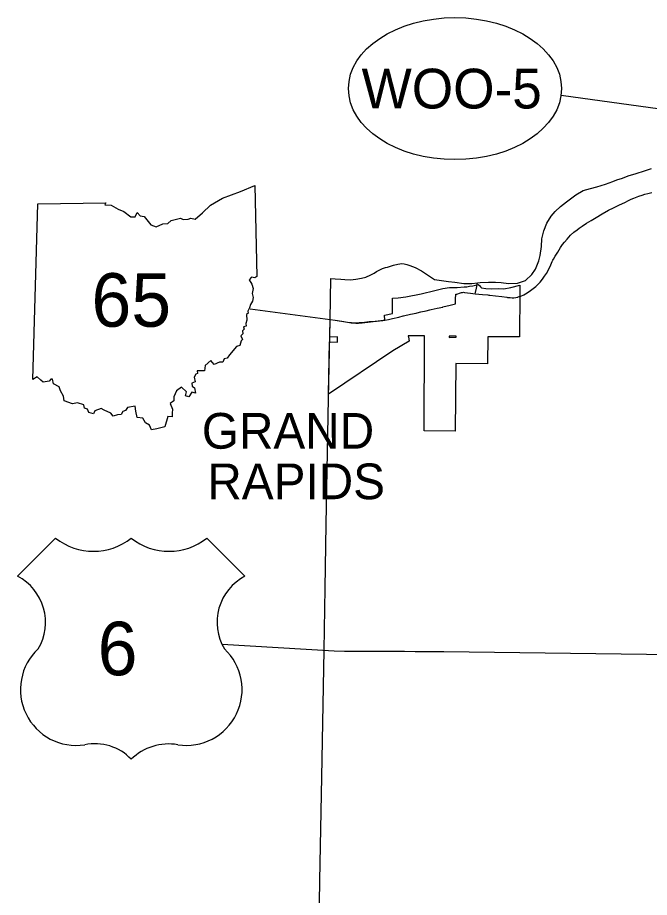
# Model space of a CAD drawing. Extents: x 0 to 851, y 0 to 440.
# Drawn here: x 185.2 to 229.7, y 193.8 to 255.7 of the extents above; entities that cross this region are included whole.
import ezdxf

# ---------------------------------------------------------------- set-up
doc = ezdxf.new("R2010")
doc.units = 0
for name, color, linetype in [('DV_X_Corp_Line', 7, 'Continuous'), ('GM_X_Corporation_Text', 7, 'Continuous'), ('GM_X_County', 7, 'Continuous'), ('GM_X_State_Route', 7, 'Continuous'), ('GM_X_US_Route', 7, 'Continuous'), ('PV_P_Text', 7, 'Continuous'), ('SH_Data', 7, 'Continuous')]:
    doc.layers.add(name, color=color, linetype=linetype)

msp = doc.modelspace()

# ---------------------------------------------------------------- linework, layer by layer
at = {"layer": 'DV_X_Corp_Line'}
for points in [[(207.099, 229.174), (207.166, 232.861), (207.728, 232.851), (207.727, 233.209), (207.172, 233.196), (207.194, 234.435), (207.555, 234.386), (208.426, 234.255), (208.697, 234.216), (208.861, 234.196), (209.001, 234.183), (209.189, 234.182), (209.452, 234.203), (209.867, 234.251), (210.228, 234.29), (210.903, 234.365), (211.063, 234.39), (211.022, 234.744), (211.59, 234.85), (211.6, 235.946), (211.998, 235.975), (212.541, 236.039), (213.614, 236.257), (214.57, 236.473), (215.131, 236.63), (215.604, 236.701), (216.143, 236.694), (216.632, 236.736), (216.832, 236.736), (217.007, 236.778), (217.249, 236.803), (217.617, 236.903), (217.723, 236.834), (217.785, 236.742), (217.867, 236.67), (218.16, 236.632), (218.554, 236.603), (219.043, 236.614), (219.427, 236.595), (219.927, 236.696), (220.57, 236.863), (220.559, 236.094), (220.533, 233.48), (220.532, 233.209), (218.318, 233.211), (218.278, 231.326), (216.053, 231.342), (216.013, 226.569), (213.821, 226.6), (213.853, 233.291), (212.996, 233.287), (212.699, 233.279), (212.737, 233.068), (212.762, 232.923), (211.615, 232.228)], [(215.58, 233.258), (215.58, 233.18), (216.071, 233.188), (216.071, 233.267)]]:
    msp.add_lwpolyline(points, close=True, dxfattribs=at)
at = {"layer": 'GM_X_County'}
msp.add_lwpolyline([(206.451, 193.368), (206.479, 194.938), (206.611, 202.226), (206.773, 211.151), (206.852, 215.518), (206.933, 220.004), (207.094, 228.895), (207.194, 234.435), (207.247, 237.334), (207.546, 237.297), (207.945, 237.27), (208.231, 237.261), (208.627, 237.241), (209.014, 237.285), (209.411, 237.338), (209.712, 237.42), (210.071, 237.572), (210.298, 237.702), (210.468, 237.82), (210.705, 237.937), (210.888, 238.025), (211.112, 238.094), (211.239, 238.127), (211.446, 238.198), (211.672, 238.272), (211.967, 238.341), (212.247, 238.386), (212.421, 238.36), (212.592, 238.31), (212.81, 238.239), (213.191, 238.098), (213.645, 237.861), (214.118, 237.541), (214.548, 237.261), (215.216, 237.159), (215.545, 237.113), (215.982, 237.072), (216.607, 236.984), (217.179, 236.971), (217.586, 237.018), (217.759, 237.038), (218.355, 237.062), (218.854, 237.073), (219.25, 237.033), (219.765, 236.977), (220.388, 236.99), (220.96, 237.179), (221.394, 237.602), (221.667, 237.971), (221.889, 238.572), (221.989, 238.95), (222.094, 239.571), (222.1, 240.109), (222.251, 240.684), (222.458, 241.215), (222.766, 241.721), (223.038, 242.049), (223.434, 242.392), (223.847, 242.718), (224.502, 243.224), (225.008, 243.511), (225.526, 243.656), (225.989, 243.79), (226.595, 243.971), (227.1, 244.16), (227.401, 244.282), (227.787, 244.39), (228.177, 244.548), (228.749, 244.723), (229.341, 244.9), (229.822, 245.07)], dxfattribs=at)
at = {"layer": 'GM_X_State_Route'}
for points in [[(222.84, 238.512), (222.892, 238.618), (222.929, 238.687), (223.04, 238.893), (223.225, 239.191), (223.424, 239.508), (223.574, 239.726), (223.709, 239.894), (223.888, 240.084), (224.123, 240.365), (224.368, 240.583), (224.594, 240.759), (224.739, 240.862), (224.949, 241.011), (225.248, 241.214), (225.577, 241.411), (225.923, 241.613), (226.36, 241.879), (226.812, 242.126), (227.165, 242.302), (227.588, 242.507), (227.954, 242.686), (228.214, 242.813), (228.406, 242.908), (228.588, 242.987), (228.939, 243.114), (229.165, 243.198), (229.358, 243.261), (229.575, 243.319), (229.852, 243.38)], [(220.522, 236.054), (220.62, 236.088), (220.847, 236.187), (221.086, 236.312), (221.311, 236.48), (221.49, 236.611), (221.676, 236.759), (221.855, 236.937), (222.002, 237.079), (222.155, 237.282), (222.307, 237.487), (222.442, 237.682), (222.57, 237.938), (222.736, 238.296), (222.84, 238.512)], [(217.44, 236.35), (217.506, 236.652), (217.586, 237.018)], [(216.038, 235.534), (216.041, 235.926), (216.044, 236.169)], [(216.044, 236.169), (216.045, 236.222), (216.116, 236.23), (216.203, 236.251), (216.315, 236.289), (216.451, 236.336), (216.518, 236.348), (216.596, 236.352), (216.666, 236.348), (217.088, 236.297), (217.42, 236.255)], [(217.42, 236.255), (217.44, 236.349), (217.44, 236.35)], [(217.42, 236.255), (217.922, 236.205), (218.309, 236.169)], [(218.309, 236.169), (218.372, 236.163), (218.458, 236.155), (218.857, 236.105), (219.296, 236.054), (219.641, 236.004), (219.687, 235.997), (219.868, 235.982), (220.009, 235.972), (220.147, 235.975), (220.272, 235.986), (220.424, 236.019), (220.44, 236.025), (220.522, 236.054)], [(211.586, 234.514), (212.035, 234.614), (212.345, 234.693), (212.37, 234.699), (212.856, 234.808), (213.258, 234.896), (213.33, 234.913), (213.596, 234.975), (213.964, 235.053), (214.216, 235.114), (214.319, 235.139), (214.741, 235.229), (215.129, 235.317), (215.148, 235.321), (215.66, 235.441), (216.038, 235.534)], [(201.573, 235.198), (207.555, 234.386), (208.022, 234.315), (208.426, 234.255), (208.694, 234.215), (208.831, 234.195), (208.931, 234.193), (209.032, 234.204), (209.257, 234.225), (209.613, 234.261), (209.956, 234.296), (210.363, 234.331), (210.389, 234.333), (210.766, 234.368), (210.944, 234.381), (210.98, 234.385)], [(210.98, 234.385), (211.056, 234.395), (211.306, 234.447), (211.586, 234.514)]]:
    msp.add_lwpolyline(points, dxfattribs=at)
at = {"layer": 'GM_X_US_Route'}
msp.add_lwpolyline([(199.601, 211.573), (207.497, 211.109), (208.225, 211.096), (209.007, 211.093), (209.947, 211.085), (210.703, 211.089), (211.152, 211.094), (211.732, 211.091), (212.442, 211.085), (213.195, 211.075), (213.812, 211.068), (214.492, 211.059), (215.202, 211.057), (238.396, 210.754)], dxfattribs=at)
at = {"layer": 'PV_P_Text'}
for p, q in [((186.271, 230.208), (186.617, 242.581)), ((186.271, 230.208), (186.617, 242.581)), ((187.876, 219.038), (185.197, 216.359)), ((187.876, 219.038), (185.197, 216.359)), ((201.204, 216.359), (198.525, 219.038)), ((201.204, 216.359), (198.525, 219.038))]:
    msp.add_line(p, q, dxfattribs=at)
for points in [[(186.617, 242.581), (191.418, 242.661), (191.343, 242.512), (191.796, 242.48), (192.277, 242.216), (192.684, 242.049), (193.181, 241.656), (193.479, 241.66), (193.605, 241.983), (193.833, 241.734), (194.104, 241.689), (194.572, 241.097), (194.958, 240.969), (195.421, 241.172), (195.767, 241.205), (196.019, 241.406), (196.678, 241.577), (196.862, 241.475), (197.211, 241.495), (197.386, 241.571), (197.69, 241.504), (198.226, 241.953), (198.777, 242.484), (199.625, 242.984), (200.891, 243.458), (201.893, 243.883), (202.037, 237.462)], [(186.617, 242.581), (191.418, 242.661), (191.343, 242.512), (191.796, 242.48), (192.277, 242.216), (192.684, 242.049), (193.181, 241.656), (193.479, 241.66), (193.605, 241.983), (193.833, 241.734), (194.104, 241.689), (194.572, 241.097), (194.958, 240.969), (195.421, 241.172), (195.767, 241.205), (196.019, 241.406), (196.678, 241.577), (196.862, 241.475), (197.211, 241.495), (197.386, 241.571), (197.69, 241.504), (198.226, 241.953), (198.777, 242.484), (199.625, 242.984), (200.891, 243.458), (201.893, 243.883), (202.037, 237.462)], [(202.037, 237.462), (201.89, 237.372), (201.659, 237.414), (201.505, 237.234), (201.696, 236.934), (201.787, 236.616), (201.706, 236.266), (201.786, 235.978), (201.732, 235.736), (201.587, 235.496), (201.537, 235.267), (201.414, 235.025), (201.425, 234.89), (201.307, 234.783), (201.329, 234.382), (201.269, 234.159), (201.29, 233.967), (201.1, 233.917), (201.143, 233.758), (201.022, 233.636), (201.048, 233.425), (200.911, 233.29), (201.044, 233.021), (200.937, 232.936), (200.849, 232.608), (200.605, 232.542), (200.116, 231.942), (199.944, 231.716), (199.751, 231.66), (199.644, 231.427), (199.406, 231.426), (199.045, 231.265), (198.812, 231.542), (198.404, 231.208), (198.357, 230.822), (197.84, 230.835), (197.86, 230.64), (197.745, 230.583), (197.64, 230.387), (197.701, 230.04), (197.459, 229.952), (197.489, 229.75), (197.643, 229.627), (197.712, 229.242), (197.455, 229.32), (197.245, 228.995), (197.028, 229.071), (197.099, 229.346), (196.734, 229.677), (196.388, 229.412), (196.207, 228.989), (196.205, 228.704), (195.947, 228.532), (196.113, 228.129), (196.082, 227.852), (196.087, 227.589), (195.765, 227.598), (195.57, 226.888)], [(202.037, 237.462), (201.89, 237.372), (201.659, 237.414), (201.505, 237.234), (201.696, 236.934), (201.787, 236.616), (201.706, 236.266), (201.786, 235.978), (201.732, 235.736), (201.587, 235.496), (201.537, 235.267), (201.414, 235.025), (201.425, 234.89), (201.307, 234.783), (201.329, 234.382), (201.269, 234.159), (201.29, 233.967), (201.1, 233.917), (201.143, 233.758), (201.022, 233.636), (201.048, 233.425), (200.911, 233.29), (201.044, 233.021), (200.937, 232.936), (200.849, 232.608), (200.605, 232.542), (200.116, 231.942), (199.944, 231.716), (199.751, 231.66), (199.644, 231.427), (199.406, 231.426), (199.045, 231.265), (198.812, 231.542), (198.404, 231.208), (198.357, 230.822), (197.84, 230.835), (197.86, 230.64), (197.745, 230.583), (197.64, 230.387), (197.701, 230.04), (197.459, 229.952), (197.489, 229.75), (197.643, 229.627), (197.712, 229.242), (197.455, 229.32), (197.245, 228.995), (197.028, 229.071), (197.099, 229.346), (196.734, 229.677), (196.388, 229.412), (196.207, 228.989), (196.205, 228.704), (195.947, 228.532), (196.113, 228.129), (196.082, 227.852), (196.087, 227.589), (195.765, 227.598), (195.57, 226.888)], [(195.57, 226.888), (195.01, 226.752), (194.621, 226.671), (194.484, 226.994), (194.206, 227.164), (194.025, 227.489), (193.625, 227.533), (193.531, 227.979), (193.486, 228.341), (192.94, 228.252), (192.79, 228.03), (192.597, 227.971), (192.484, 227.748), (192.22, 227.729), (191.937, 227.624), (191.752, 227.843), (191.288, 228.062), (191.079, 228.176), (190.643, 228), (190.55, 227.791), (190.202, 227.883), (190.121, 228.116), (189.911, 228.185), (189.864, 228.432), (189.415, 228.563), (189.072, 228.511), (188.466, 228.709), (188.429, 229.033), (188.222, 229.428), (188.115, 229.703), (187.732, 229.912), (187.654, 230.238), (187.531, 230.229), (187.419, 230.096), (186.994, 230.036), (186.824, 230.169), (186.586, 230.396), (186.271, 230.208)], [(195.57, 226.888), (195.01, 226.752), (194.621, 226.671), (194.484, 226.994), (194.206, 227.164), (194.025, 227.489), (193.625, 227.533), (193.531, 227.979), (193.486, 228.341), (192.94, 228.252), (192.79, 228.03), (192.597, 227.971), (192.484, 227.748), (192.22, 227.729), (191.937, 227.624), (191.752, 227.843), (191.288, 228.062), (191.079, 228.176), (190.643, 228), (190.55, 227.791), (190.202, 227.883), (190.121, 228.116), (189.911, 228.185), (189.864, 228.432), (189.415, 228.563), (189.072, 228.511), (188.466, 228.709), (188.429, 229.033), (188.222, 229.428), (188.115, 229.703), (187.732, 229.912), (187.654, 230.238), (187.531, 230.229), (187.419, 230.096), (186.994, 230.036), (186.824, 230.169), (186.586, 230.396), (186.271, 230.208)]]:
    msp.add_lwpolyline(points, dxfattribs=at)
for centre, radius, start, end in [((190.539, 222.423), 4.306, 231.81301, 308.18697), ((190.539, 222.423), 4.306, 231.81301, 308.18697), ((195.863, 222.423), 4.306, 231.81301, 308.18697), ((195.863, 222.423), 4.306, 231.81301, 308.18697), ((183.522, 213.125), 3.642, 329.11751, 62.61081), ((183.522, 213.125), 3.642, 329.11751, 62.61081), ((202.88, 213.125), 3.642, 117.38919, 210.88249), ((202.88, 213.125), 3.642, 117.38919, 210.88249), ((189.328, 208.382), 3.93, 133.00455, 278.72816), ((189.328, 208.382), 3.93, 133.00455, 278.72816), ((197.074, 208.382), 3.93, 261.27184, 46.99545), ((197.074, 208.382), 3.93, 261.27184, 46.99545), ((190.648, 201.058), 3.515, 43.41772, 101.87423), ((190.648, 201.058), 3.515, 43.41772, 101.87423), ((195.827, 200.825), 3.731, 79.96126, 134.74679), ((195.827, 200.825), 3.731, 79.96126, 134.74679)]:
    msp.add_arc(centre, radius, start, end, dxfattribs=at)
at = {"layer": 'SH_Data'}
msp.add_line((223.462, 250.235), (295.053, 240.313), dxfattribs=at)
msp.add_ellipse((215.994, 250.695), major_axis=(7.5, 0), ratio=0.666667, dxfattribs=at)

# ---------------------------------------------------------------- texts
at = {"layer": 'GM_X_Corporation_Text'}
for s, p in [('GRAND', (198.17, 225.344)), ('RAPIDS', (198.556, 221.787))]:
    msp.add_text(s, height=2.5126, rotation=0.00001, dxfattribs=at).set_placement(p)
at = {"layer": 'PV_P_Text'}
for s, height, p in [('65', 3.7688, (190.399, 233.93)), ('6', 3.769, (190.835, 209.391))]:
    msp.add_text(s, height=height, dxfattribs=at).set_placement(p)
at = {"layer": 'SH_Data'}
msp.add_text('WOO-5', height=2.8, dxfattribs=at).set_placement((209.418, 249.295))

doc.saveas('drawing.dxf')
